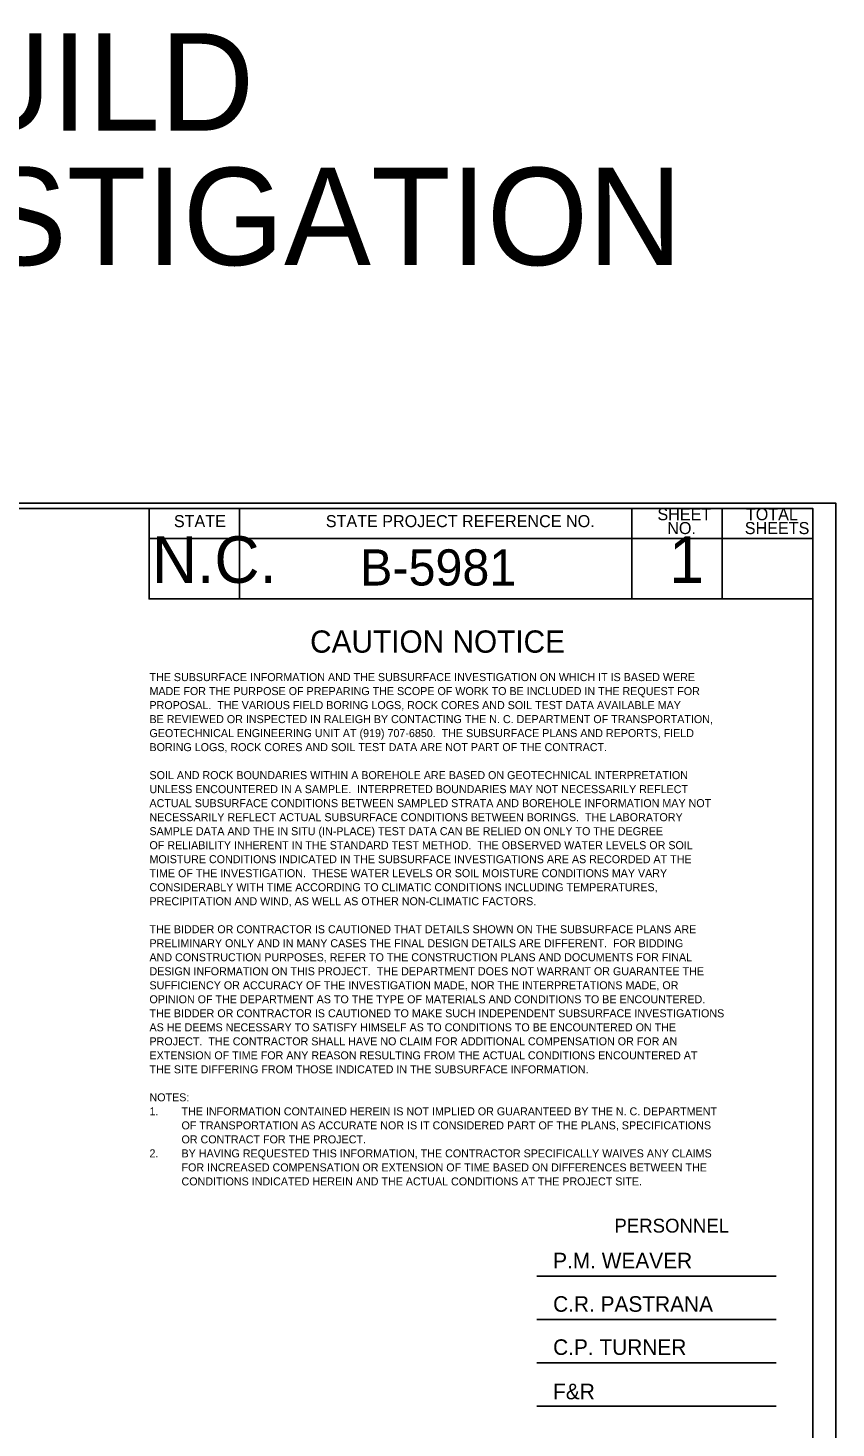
# Model space of a CAD drawing. Extents: x 265553 to 275568, y 168312 to 173522.
# Drawn here: x 273778 to 274213, y 172697 to 173452 of the extents above; entities that cross this region are included whole.
import ezdxf

# ---------------------------------------------------------------- set-up
doc = ezdxf.new("R2010")
doc.units = 0
for name, color, linetype in [('Geotech Sheets and Borders Cell', 7, 'Continuous'), ('Scratch_Level_0', 7, 'Continuous'), ('Scratch_Level_2', 7, 'Continuous'), ('Sheet Plot Border Inside CELL', 7, 'Continuous')]:
    doc.layers.add(name, color=color, linetype=linetype)

msp = doc.modelspace()

# ---------------------------------------------------------------- linework, layer by layer
at = {"layer": 'Geotech Sheets and Borders Cell'}
for p, q in [((273891.94, 173192.56), (273891.94, 173143.83)), ((274103.21, 173192.56), (274103.21, 173143.83)), ((274151.95, 173192.57), (274151.95, 173143.84)), ((273843.19, 173176.33), (274200.69, 173176.33)), ((274051.99, 172778.89), (274180.95, 172778.89)), ((274051.99, 172755.49), (274180.95, 172755.49)), ((274051.99, 172732.09), (274180.95, 172732.09)), ((274051.99, 172708.69), (274180.95, 172708.69))]:
    msp.add_line(p, q, dxfattribs=at)
for points in [[(272700.69, 173192.58), (274200.69, 173192.58), (274200.69, 172142.58), (272700.69, 172142.58)], [(273843.19, 173192.58), (274200.69, 173192.58), (274200.69, 173143.83), (273843.19, 173143.83)]]:
    msp.add_lwpolyline(points, close=True, dxfattribs=at)
at = {"layer": 'Scratch_Level_0'}
msp.add_line((274213.19, 173195.41), (274213.19, 173195.41), dxfattribs=at)
at = {"layer": 'Sheet Plot Border Inside CELL'}
msp.add_lwpolyline([(272545.53, 172139.74), (274213.19, 172139.74), (274213.19, 173195.41), (272545.53, 173195.41)], close=True, dxfattribs=at)

# ---------------------------------------------------------------- texts
at = {"layer": 'Geotech Sheets and Borders Cell'}
for s, height, p in [('STATE', 6.5, (273856.51, 173182.49)), ('STATE PROJECT REFERENCE NO.', 6.4997, (273938.34, 173182.49)), ('SHEET', 6.5, (274116.99, 173186.22)), ('TOTAL', 6.5, (274164.65, 173186.22)), ('NO.', 6.5, (274122.28, 173178.75)), ('SHEETS', 6.5, (274164.07, 173178.75)), ('N.C.', 25.155, (273844.69, 173152.45)), ('B-5981', 19.5, (273956.85, 173151.04)), ('1', 25.16, (274123.32, 173152.45)), ('CAUTION NOTICE', 12, (273929.91, 173114.83)), ('THE SUBSURFACE INFORMATION AND THE SUBSURFACE INVESTIGATION ON WHICH IT IS BASED WERE', 4.3142, (273843.36, 173099.52)), ('MADE FOR THE PURPOSE OF PREPARING THE SCOPE OF WORK TO BE INCLUDED IN THE REQUEST FOR', 4.3142, (273843.36, 173091.98)), ('PROPOSAL.  THE VARIOUS FIELD BORING LOGS, ROCK CORES AND SOIL TEST DATA AVAILABLE MAY', 4.3142, (273843.36, 173084.43)), ('BE REVIEWED OR INSPECTED IN RALEIGH BY CONTACTING THE N. C. DEPARTMENT OF TRANSPORTATION,', 4.3142, (273843.36, 173076.88)), ('GEOTECHNICAL ENGINEERING UNIT AT (919) 707-6850.  THE SUBSURFACE PLANS AND REPORTS, FIELD', 4.3142, (273843.36, 173069.33)), ('BORING LOGS, ROCK CORES AND SOIL TEST DATA ARE NOT PART OF THE CONTRACT.', 4.3142, (273843.36, 173061.78)), ('SOIL AND ROCK BOUNDARIES WITHIN A BOREHOLE ARE BASED ON GEOTECHNICAL INTERPRETATION', 4.3142, (273843.36, 173046.68)), ('UNLESS ENCOUNTERED IN A SAMPLE.  INTERPRETED BOUNDARIES MAY NOT NECESSARILY REFLECT', 4.3142, (273843.36, 173039.13)), ('ACTUAL SUBSURFACE CONDITIONS BETWEEN SAMPLED STRATA AND BOREHOLE INFORMATION MAY NOT', 4.3142, (273843.36, 173031.58)), ('NECESSARILY REFLECT ACTUAL SUBSURFACE CONDITIONS BETWEEN BORINGS.  THE LABORATORY', 4.3142, (273843.36, 173024.03)), ('SAMPLE DATA AND THE IN SITU (IN-PLACE) TEST DATA CAN BE RELIED ON ONLY TO THE DEGREE', 4.3142, (273843.36, 173016.48)), ('OF RELIABILITY INHERENT IN THE STANDARD TEST METHOD.  THE OBSERVED WATER LEVELS OR SOIL', 4.3142, (273843.36, 173008.93)), ('MOISTURE CONDITIONS INDICATED IN THE SUBSURFACE INVESTIGATIONS ARE AS RECORDED AT THE', 4.3142, (273843.36, 173001.38)), ('TIME OF THE INVESTIGATION.  THESE WATER LEVELS OR SOIL MOISTURE CONDITIONS MAY VARY', 4.3142, (273843.36, 172993.83)), ('CONSIDERABLY WITH TIME ACCORDING TO CLIMATIC CONDITIONS INCLUDING TEMPERATURES,', 4.3142, (273843.36, 172986.28)), ('PRECIPITATION AND WIND, AS WELL AS OTHER NON-CLIMATIC FACTORS.', 4.3142, (273843.36, 172978.73)), ('THE BIDDER OR CONTRACTOR IS CAUTIONED THAT DETAILS SHOWN ON THE SUBSURFACE PLANS ARE', 4.3142, (273843.36, 172963.63)), ('PRELIMINARY ONLY AND IN MANY CASES THE FINAL DESIGN DETAILS ARE DIFFERENT.  FOR BIDDING', 4.3142, (273843.36, 172956.08)), ('AND CONSTRUCTION PURPOSES, REFER TO THE CONSTRUCTION PLANS AND DOCUMENTS FOR FINAL', 4.3142, (273843.36, 172948.53)), ('DESIGN INFORMATION ON THIS PROJECT.  THE DEPARTMENT DOES NOT WARRANT OR GUARANTEE THE', 4.3142, (273843.36, 172940.98)), ('SUFFICIENCY OR ACCURACY OF THE INVESTIGATION MADE, NOR THE INTERPRETATIONS MADE, OR', 4.3142, (273843.36, 172933.43)), ('OPINION OF THE DEPARTMENT AS TO THE TYPE OF MATERIALS AND CONDITIONS TO BE ENCOUNTERED.', 4.3142, (273843.36, 172925.88)), ('THE BIDDER OR CONTRACTOR IS CAUTIONED TO MAKE SUCH INDEPENDENT SUBSURFACE INVESTIGATIONS', 4.3142, (273843.36, 172918.33)), ('AS HE DEEMS NECESSARY TO SATISFY HIMSELF AS TO CONDITIONS TO BE ENCOUNTERED ON THE', 4.3142, (273843.36, 172910.78)), ('PROJECT.  THE CONTRACTOR SHALL HAVE NO CLAIM FOR ADDITIONAL COMPENSATION OR FOR AN', 4.3142, (273843.36, 172903.23)), ('EXTENSION OF TIME FOR ANY REASON RESULTING FROM THE ACTUAL CONDITIONS ENCOUNTERED AT', 4.3142, (273843.36, 172895.68)), ('THE SITE DIFFERING FROM THOSE INDICATED IN THE SUBSURFACE INFORMATION.', 4.3142, (273843.36, 172888.13)), ('NOTES:', 4.314, (273843.36, 172873.03)), ('1.', 4.314, (273843.36, 172865.48)), ('THE INFORMATION CONTAINED HEREIN IS NOT IMPLIED OR GUARANTEED BY THE N. C. DEPARTMENT', 4.3142, (273860.62, 172865.48)), ('OF TRANSPORTATION AS ACCURATE NOR IS IT CONSIDERED PART OF THE PLANS, SPECIFICATIONS', 4.3142, (273860.62, 172857.93)), ('OR CONTRACT FOR THE PROJECT.', 4.3142, (273860.62, 172850.38)), ('2.', 4.314, (273843.36, 172842.83)), ('BY HAVING REQUESTED THIS INFORMATION, THE CONTRACTOR SPECIFICALLY WAIVES ANY CLAIMS', 4.3142, (273860.62, 172842.83)), ('FOR INCREASED COMPENSATION OR EXTENSION OF TIME BASED ON DIFFERENCES BETWEEN THE', 4.3142, (273860.62, 172835.28)), ('CONDITIONS INDICATED HEREIN AND THE ACTUAL CONDITIONS AT THE PROJECT SITE.', 4.3142, (273860.62, 172827.73)), ('PERSONNEL', 7.488, (274093.83, 172802.29)), ('P.M. WEAVER', 8.4, (274060.81, 172783.02)), ('C.R. PASTRANA', 8.4, (274060.81, 172759.62)), ('C.P. TURNER', 8.4, (274060.81, 172736.37)), ('F&R', 8.4, (274060.81, 172712.46))]:
    msp.add_text(s, height=height, dxfattribs=at).set_placement(p)
at = {"layer": 'Scratch_Level_2'}
for s, p in [('w/ 2 SEAL BOXES for DESIGN BUILD', (272694.2, 173396.21)), ('ROADWAY SUBSURFACE INVESTIGATION', (272706.6, 173323.71))]:
    msp.add_text(s, height=52.5002, dxfattribs=at).set_placement(p)

doc.saveas('drawing.dxf')
